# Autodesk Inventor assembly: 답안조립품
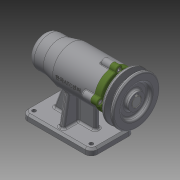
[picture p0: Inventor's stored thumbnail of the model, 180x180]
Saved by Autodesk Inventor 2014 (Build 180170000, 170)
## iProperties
Created: 2019-07
Part Number: 답안조립품
Document SubType Name: Assembly
Designer: kh
Author: kh
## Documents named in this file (12)
- C:\Users\kh\Desktop\490704V1080\답안조립품.iam
- C:\Users\kh\Desktop\490704V1080\본체.ipt
- C:\Users\kh\Desktop\490704V1080\축.ipt
- C:\Users\kh\Desktop\490704V1080\베어링 6004.ipt
- C:\Users\kh\Desktop\490704V1080\어댑터슬리브.ipt
- C:\Users\kh\Desktop\490704V1080\볼트 M4.ipt
- C:\Users\kh\Desktop\490704V1080\베어링 51202.ipt
- C:\Users\kh\Desktop\490704V1080\커버.ipt
- C:\Users\kh\Desktop\490704V1080\키 5 x 5 x 16.ipt
- C:\Users\kh\Desktop\490704V1080\멈춤나사 M3.ipt
- C:\Users\kh\Desktop\490704V1080\V벨트풀리.ipt
- C:\Users\kh\Desktop\490704V1080\오일 실.ipt
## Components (1 placed, 1 different names)
1. V벨트풀리:1 — Mate:11, Mate:12, Flush:1, Angle:1
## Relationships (4: Mate 2, Flush 1, Angle 1)
- Mate:11: V벨트풀리:1
- Mate:12: V벨트풀리:1
- Flush:1: V벨트풀리:1
- Angle:1: V벨트풀리:1
